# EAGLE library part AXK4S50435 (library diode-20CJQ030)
Matsushita P6 NARROW-PITCH CONNECTORS FOR PC BOARDS 50Pin Header NARROW-PITCH (0.6mm) CONNECTORS P6 SERIES FEATURES The product lineup consists of the low profile of: - 3 mm - 4 mm - 5 mm - 6 mm - 7 mm - 8 mm - 9 mm APPLICATIONS Small portable equipment, laptop computers, video equipment, radio communication, cellular telephones, etc. Please send any comments to: messi@users.sourceforge.net
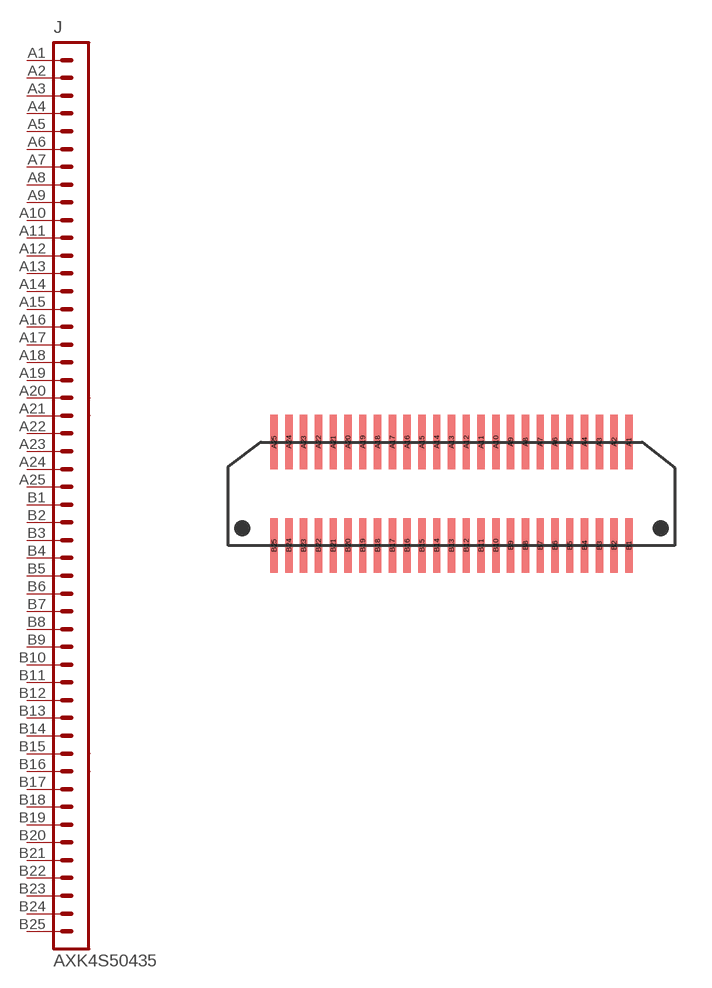
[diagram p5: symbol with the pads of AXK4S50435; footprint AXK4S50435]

Designator prefix J

## AXK4S50435  [AXK4S50435]
A1  1  pas
A2  2  pas
A3  3  pas
A4  4  pas
A5  5  pas
A6  6  pas
A7  7  pas
A8  8  pas
A9  9  pas
A10  10  pas
A11  11  pas
A12  12  pas
A13  13  pas
A14  14  pas
A15  15  pas
A16  16  pas
A17  17  pas
A18  18  pas
A19  19  pas
A20  20  pas
A21  21  pas
A22  22  pas
A23  23  pas
A24  24  pas
A25  25  pas
B1  26  pas
B2  27  pas
B3  28  pas
B4  29  pas
B5  30  pas
B6  31  pas
B7  32  pas
B8  33  pas
B9  34  pas
B10  35  pas
B11  36  pas
B12  37  pas
B13  38  pas
B14  39  pas
B15  40  pas
B16  41  pas
B17  42  pas
B18  43  pas
B19  44  pas
B20  45  pas
B21  46  pas
B22  47  pas
B23  48  pas
B24  49  pas
B25  50  pas

## Footprint AXK4S50435 (pad centres in mm)
Matsushita NARROW-PITCH CONNECTORS FOR PC BOARDS 50Pin Header NARROW-PITCH (0.6mm) CONNECTORS P6 SERIES FEATURES The product lineup consists of the low profile of: - 3 mm - 4 mm - 5 mm - 6 mm - 7 mm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
smd 0.3 x 2.2: A1 7.2,2.1; A2 6.6,2.1; A3 6,2.1; A4 5.4,2.1; A5 4.8,2.1; A6 4.2,2.1; A7 3.6,2.1; A8 3,2.1; A9 2.4,2.1; A10 1.8,2.1; A11 1.2,2.1; A12 0.6,2.1; A13 0,2.1; A14 -0.6,2.1; A15 -1.2,2.1; A16 -1.8,2.1; A17 -2.4,2.1; A18 -3,2.1; A19 -3.6,2.1; A20 -4.2,2.1; A21 -4.8,2.1; A22 -5.4,2.1; A23 -6,2.1; A24 -6.6,2.1; A25 -7.2,2.1; B1 7.2,-2.1; B2 6.6,-2.1; B3 6,-2.1; B4 5.4,-2.1; B5 4.8,-2.1; B6 4.2,-2.1; B7 3.6,-2.1; B8 3,-2.1; B9 2.4,-2.1; B10 1.8,-2.1; B11 1.2,-2.1; B12 0.6,-2.1; B13 0,-2.1; B14 -0.6,-2.1; B15 -1.2,-2.1; B16 -1.8,-2.1; B17 -2.4,-2.1; B18 -3,-2.1; B19 -3.6,-2.1; B20 -4.2,-2.1; B21 -4.8,-2.1; B22 -5.4,-2.1; B23 -6,-2.1; B24 -6.6,-2.1; B25 -7.2,-2.1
